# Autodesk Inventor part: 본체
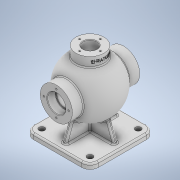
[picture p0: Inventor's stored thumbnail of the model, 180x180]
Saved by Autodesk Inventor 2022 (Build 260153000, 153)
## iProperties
Created: 2024-04
Part Number: 본체
Material: 일반
Document SubType Name: Modeling
Designer: Admin
Density: 1 g/cm^3
Appearance: 기본값
Author: Admin
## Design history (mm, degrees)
sketch "스케치1"
  geometry: L1 (0, 25.672)-(0, -13.488); L2 (0, 54)-(0, -54); A1 r 54 centre (0, 0) between (0, -54) and (0, 54); 3 further points
  constraints: 4 end point, 3 point on line, 2 point on circle, 2 vertical, 1 centre point, 1 coincident
  dimensions: "d0" = 54 radius of A1
revolve "회전1" sketch "스케치1" stored, may be unused: angle "d1" = 90 deg
node "작업 평면1"
sketch "스케치2"
  geometry: C1 r 31 at (0, 0); 1 further point
  constraints: 1 centre point, 1 coincident
  dimensions: "d3" = 62 diameter of C1
extrude "돌출1" join sketch "스케치2" stored distance "d4" = 10; taper "d5" = 0 deg
node "작업 평면2"
sketch "스케치3"
  geometry: C1 r 27 at (0, 0); 1 further point
  constraints: 1 centre point, 1 coincident
  dimensions: "d10" = 54 diameter of C1
extrude "돌출2" join sketch "스케치3" stored distance "d11" = 10; taper "d12" = 0 deg
node "작업 평면3"
sketch "스케치4"
  geometry: L1 (62.5, -62.5)-(-62.5, -62.5); L2 (-62.5, -62.5)-(-62.5, 62.5); L3 (-62.5, 62.5)-(62.5, 62.5); L4 (62.5, 62.5)-(62.5, -62.5); L5 (62.5, -62.5)-(-62.5, 62.5); L6 (-62.5, -62.5)-(62.5, 62.5); 1 further point
  constraints: 12 end point, 2 midpoint, 2 parallel, 1 horizontal, 1 perpendicular
  dimensions: "d14" = 125 distance of L2.end L3.end; "d15" = 125 distance of L1.end L2.end
extrude "돌출3" join sketch "스케치4" distance "d16" = 10; taper "d17" = 0 deg
sketch "스케치5"
  geometry: L1 (-50.5, 4)-(50.5, 4); L2 (50.5, 4)-(50.5, -4); L3 (50.5, -4)-(-50.5, -4); L4 (-50.5, -4)-(-50.5, 4); L5 (-50.5, 4)-(50.5, -4); L6 (50.5, 4)-(-50.5, -4); L7 (-4, -50.5)-(4, -50.5); L8 (4, -50.5)-(4, 50.5); L9 (4, 50.5)-(-4, 50.5); L10 (-4, 50.5)-(-4, -50.5); L11 (-4, -50.5)-(4, 50.5); L12 (4, -50.5)-(-4, 50.5); 5 further points
  constraints: 24 end point, 4 midpoint, 4 parallel, 2 horizontal, 2 perpendicular
  dimensions: "d18" = 101 distance of L2.end L3.end; "d19" = 8 distance of L1.end L2.end; "d20" = 8 distance of L9.end L8.end; "d21" = 101 distance of L8.end L7.end
extrude "돌출4" join sketch "스케치5" stored distance "d22" = 10; taper "d23" = 0 deg
feature "면 기울기1" dims angle "d24" = 20 deg
feature "면 기울기2" dims angle "d25" = 20 deg
feature "면 기울기3" dims angle "d26" = 20 deg
feature "면 기울기4" dims angle "d27" = 20 deg
sketch "스케치6"
  geometry: L1 (0, -44)-(0, 44); A1 r 44 centre (0, 0) between (0, -44) and (0, 44); 1 further point
  constraints: 2 end point, 2 point on circle, 1 centre point, 1 coincident, 1 midpoint, 1 vertical
  dimensions: "d28" = 44 radius of A1
revolve "회전2" sketch "스케치6" stored, may be unused: angle "d29" = 90 deg
sketch "스케치7"
  geometry: C1 r 17.5 at (0, 0); 1 further point
  constraints: 1 centre point, 1 coincident
  dimensions: "d30" = 35 diameter of C1
extrude "돌출5" cut sketch "스케치7" distance "d31" = 16; taper "d32" = 0 deg
sketch "스케치9"
  geometry: C1 r 15 at (0, 0); 1 further point
  constraints: 1 centre point, 1 coincident
  dimensions: "d39" = 30 diameter of C1
extrude "돌출7" cut sketch "스케치9" stored distance "d40" = 30; taper "d41" = 0 deg
sketch "스케치10"
  geometry: C1 r 13 at (0, 0); 1 further point
  constraints: 1 centre point, 1 coincident
  dimensions: "d45" = 26 diameter of C1
extrude "돌출8" cut sketch "스케치10" stored distance "d46" = 10; taper "d47" = 0 deg
sketch "스케치11"
  geometry: A1 r 24 centre (0, 0) between (0, 24) and (-24, 0); 3 further points
  constraints: 4 point on circle, 2 horizontal alignment, 2 vertical alignment, 1 centre point, 1 coincident
  dimensions: "d48" = 48 diameter of A1
hole "구멍1" sketch "스케치11" at (0, 24), (-24, 0), (0, -24), (24, 0) diameter "d49" = 3.242; stored, may be unused: countersink angle "d53" = 90 deg, drill point angle "d55" = 118 deg; dims "d50" = 12, "d51" = 12, "d52" = 5, "d54" = 15
sketch "스케치12"
  geometry: C1 r 27 at (0, 0) reference; A1 r 20 centre (0, 0) between (-20, 0) and (0, -20); 3 further points
  constraints: 4 point on circle, 2 horizontal alignment, 2 vertical alignment, 1 centre point, 1 coincident
  dimensions: "d59" = 40 diameter of A1
hole "구멍2" sketch "스케치12" at (-20, 0), (0, -20), (0, 20), (20, 0) diameter "d60" = 3.242; stored, may be unused: countersink angle "d64" = 90 deg, drill point angle "d66" = 118 deg; dims "d61" = 9, "d62" = 4, "d63" = 2, "d65" = 11
fillet "모깎기1" dims "d67" = 16
sketch "스케치13"
  geometry: C1 r 5.5 at (-46.5, 46.5); C2 r 5.5 at (46.5, 46.5); C3 r 5.5 at (46.5, -46.5); C4 r 5.5 at (-46.5, -46.5); A1 r 16 centre (-46.5, 46.5) between (-46.5, 62.5) and (-62.5, 46.5) reference; A2 r 16 centre (46.5, 46.5) between (62.5, 46.5) and (46.5, 62.5) reference; A3 r 16 centre (46.5, -46.5) between (46.5, -62.5) and (62.5, -46.5) reference; A4 r 16 centre (-46.5, -46.5) between (-62.5, -46.5) and (-46.5, -62.5) reference; 1 further point
  constraints: 4 centre point, 4 coincident
  dimensions: "d68" = 11 diameter of C1; "d69" = 11 diameter of C2; "d70" = 11 diameter of C3; "d71" = 11 diameter of C4
extrude "돌출9" cut sketch "스케치13" stored distance "d72" = 10; taper "d73" = 0 deg
node "작업 평면4"
sketch "스케치14"
  geometry: L1 (65, -27)-(65, 27) reference; L2 (-115, 0)-(95, 0) reference; 2 further points
  constraints: 1 point on line, 1 other
  dimensions: "d75" = 9 distance from line of L1 point (56, 0)
feature "엠보싱1" sketch "스케치14" dims "d0" = 54, "d76" = 0.5, "d77" = 0
fillet "모깎기2" dims "d78" = 3
fillet "모깎기3" dims "d79" = 3
fillet "모깎기4" dims "d80" = 3
fillet "모깎기5" dims "d81" = 3
chamfer "모따기1" distance "d82" = 1; stored, may be unused: second distance "d83" = 2, angle "d84" = 45 deg
fillet "모깎기6" dims "d85" = 0.6
node "솔리드1"
pattern_circular "원형 패턴1" dims angle "d7" = 360 deg
pattern_circular "원형 패턴2" dims angle "d37" = 360 deg
pattern_circular "원형 패턴3" dims angle "d43" = 360 deg
pattern_circular "원형 패턴4" dims angle "d57" = 360 deg
feature "A9D066F2-1C7D-4E18-AEED-F7BC21143FA4" dims "d49" = 3.242, "d50" = 12, "d51" = 12, "d52" = 5, "d53" = 90 deg, "d54" = 15, "d55" = 118 deg
other parameters: "d2" = 65, "d9" = 65, "d13" = -85, "d74" = 35
